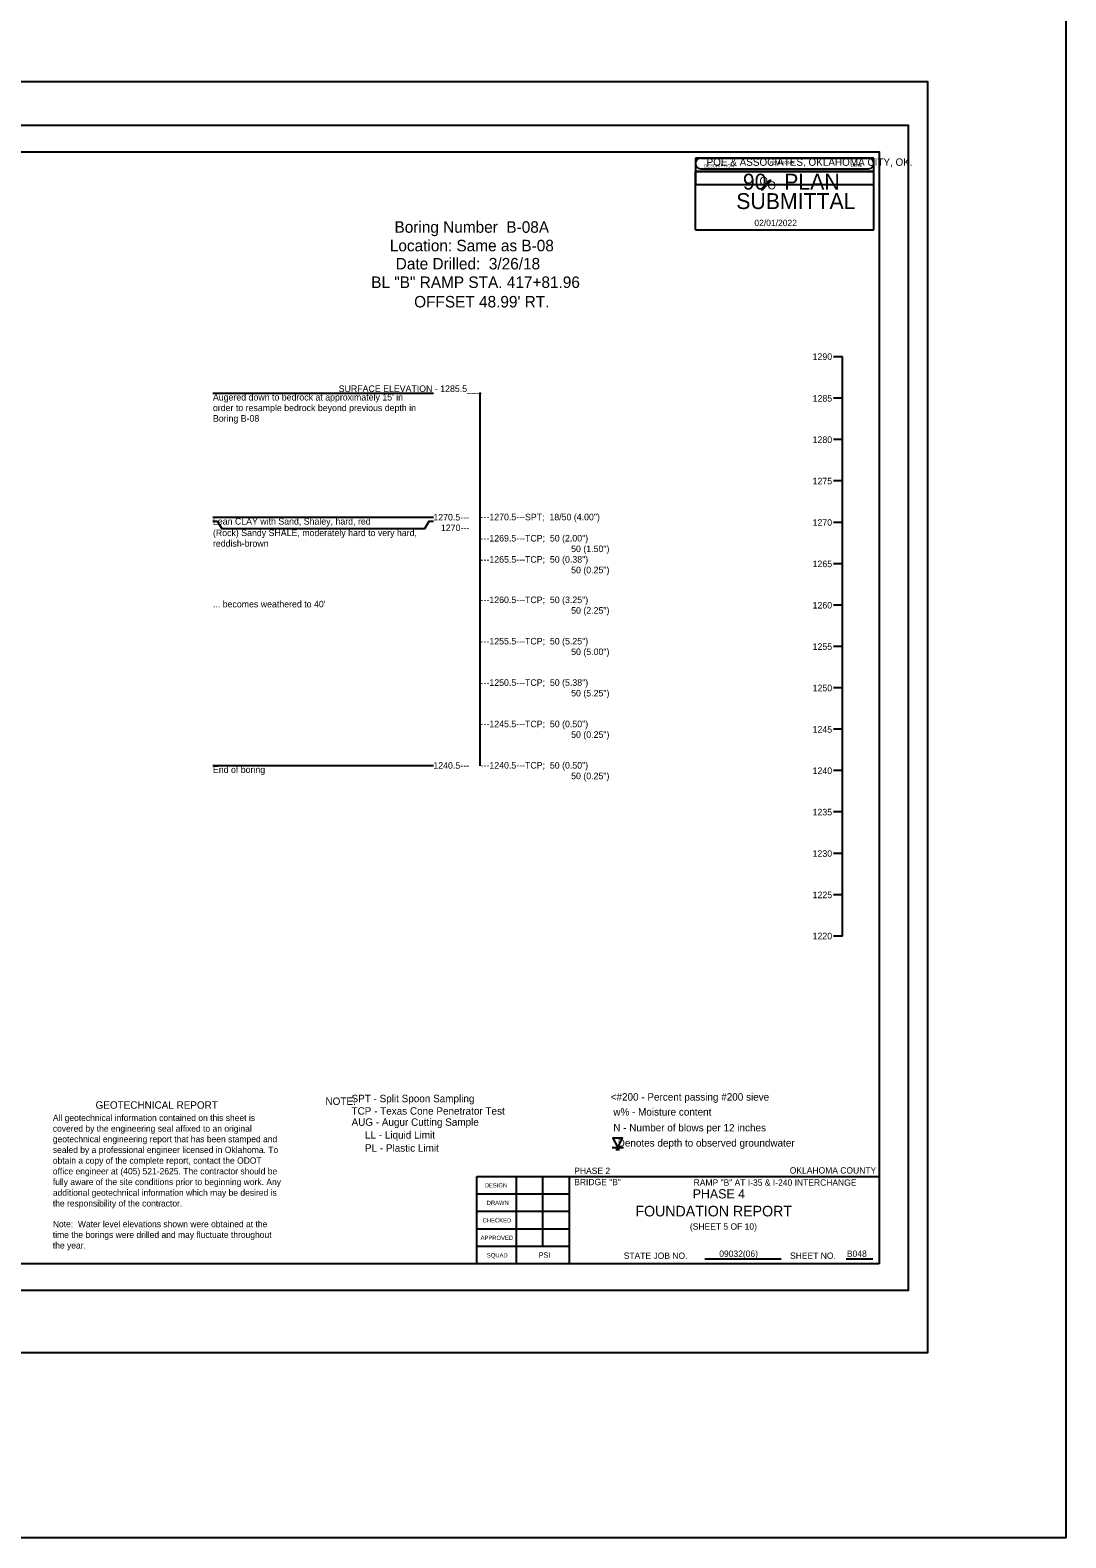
# Model space of a CAD drawing. Extents: x 2150162 to 2150245, y 143729 to 143865.
# Drawn here: x 2150183.85 to 2150203.4, y 143729.32 to 143757.78 of the extents above; entities that cross this region are included whole.
import ezdxf

# ---------------------------------------------------------------- set-up
doc = ezdxf.new("R2010")
doc.units = 0
for name, color, linetype in [('Default', 7, 'Continuous'), ('S', 7, 'Continuous'), ('SHT_Plot_Shape_Full', 7, 'Continuous'), ('SHT_Plot_Shape_Half', 7, 'Continuous'), ('SHT_Sheet_Border', 7, 'Continuous'), ('SHT_Stamp_90_Submit', 7, 'Continuous'), ('SHT_Stamp_Rev_Block', 7, 'Continuous'), ('SHT_Standard_Sheet_Lines', 7, 'Continuous'), ('SHT_Standard_Sheet_Txt', 7, 'Continuous'), ('T', 7, 'Continuous'), ('T-Title', 7, 'Continuous'), ('Text', 7, 'Continuous')]:
    doc.layers.add(name, color=color, linetype=linetype)

# ---------------------------------------------------------------- blocks, each defined once
blk = doc.blocks.new('DGRFC_WTLEV1')
at = {"layer": 'Default'}
for points in [[(-0.0127, 0), (0.0127, 0)], [(0, 0), (0.0106, 0.0212), (-0.0106, 0.0212), (0, 0)], [(-0.0042, -0.0042), (0.0042, -0.0042)]]:
    blk.add_lwpolyline(points, dxfattribs=at)

msp = doc.modelspace()

# ---------------------------------------------------------------- linework, layer by layer
at = {"layer": 'Default'}
msp.add_line((2150199.186, 143740.676), (2150199.186, 143751.613), dxfattribs=at)
for points in [[(2150199.186, 143751.613), (2150199.019, 143751.613)], [(2150187.299, 143750.929), (2150191.466, 143750.929)], [(2150192.338, 143750.937), (2150192.338, 143743.89)], [(2150199.186, 143750.832), (2150199.019, 143750.832)], [(2150199.186, 143750.051), (2150199.019, 143750.051)], [(2150199.186, 143749.27), (2150199.019, 143749.27)], [(2150199.186, 143749.27), (2150199.019, 143749.27)], [(2150187.299, 143748.585), (2150191.466, 143748.585)], [(2150187.299, 143748.507), (2150187.382, 143748.507), (2150187.466, 143748.369), (2150191.299, 143748.369), (2150191.382, 143748.507), (2150191.466, 143748.507)], [(2150199.186, 143748.488), (2150199.019, 143748.488)], [(2150199.186, 143747.707), (2150199.019, 143747.707)], [(2150199.186, 143746.926), (2150199.019, 143746.926)], [(2150199.186, 143746.145), (2150199.019, 143746.145)], [(2150199.186, 143745.363), (2150199.019, 143745.363)], [(2150199.186, 143744.582), (2150199.019, 143744.582)], [(2150187.299, 143743.898), (2150191.466, 143743.898)], [(2150199.186, 143743.801), (2150199.019, 143743.801)], [(2150199.186, 143743.02), (2150199.019, 143743.02)], [(2150199.186, 143742.238), (2150199.019, 143742.238)], [(2150199.186, 143741.457), (2150199.019, 143741.457)], [(2150199.186, 143740.676), (2150199.019, 143740.676)]]:
    msp.add_lwpolyline(points, dxfattribs=at)
at = {"layer": 'S'}
msp.add_lwpolyline([(2150161.568, 143784.341), (2150203.404, 143784.341), (2150203.404, 143729.315), (2150161.568, 143729.315)], close=True, dxfattribs=at)
at = {"layer": 'SHT_Plot_Shape_Full'}
msp.add_lwpolyline([(2150164.792, 143756.811), (2150200.792, 143756.811), (2150200.792, 143732.811), (2150164.792, 143732.811)], close=True, dxfattribs=at)
at = {"layer": 'SHT_Plot_Shape_Half'}
msp.add_lwpolyline([(2150166.429, 143755.986), (2150200.429, 143755.986), (2150200.429, 143733.986), (2150166.429, 143733.986)], close=True, dxfattribs=at)
at = {"layer": 'SHT_Sheet_Border'}
for p, q in [((2150192.279, 143734.486), (2150192.279, 143736.136)), ((2150192.279, 143736.136), (2150199.879, 143736.136)), ((2150194.029, 143734.486), (2150194.029, 143736.136))]:
    msp.add_line(p, q, dxfattribs=at)
msp.add_lwpolyline([(2150199.879, 143734.486), (2150168.379, 143734.486), (2150168.379, 143755.486), (2150199.879, 143755.486)], close=True, dxfattribs=at)
at = {"layer": 'SHT_Stamp_90_Submit'}
for p, q in [((2150196.51, 143755.362), (2150199.676, 143755.362)), ((2150196.41, 143755.112), (2150199.776, 143755.112)), ((2150196.41, 143754.012), (2150196.41, 143755.112)), ((2150196.51, 143755.162), (2150199.676, 143755.162)), ((2150197.653, 143754.773), (2150197.809, 143754.946)), ((2150197.671, 143754.773), (2150197.827, 143754.946)), ((2150197.676, 143754.773), (2150197.832, 143754.946)), ((2150197.684, 143754.773), (2150197.839, 143754.946)), ((2150197.809, 143754.946), (2150197.839, 143754.946)), ((2150199.776, 143754.012), (2150199.776, 143755.112)), ((2150197.653, 143754.773), (2150197.684, 143754.773)), ((2150196.41, 143754.012), (2150199.776, 143754.012))]:
    msp.add_line(p, q, dxfattribs=at)
for centre, start, end in [((2150196.51, 143755.262), 89.9952, 270), ((2150199.676, 143755.262), 270, 90.0048)]:
    msp.add_arc(centre, 0.1, start, end, dxfattribs=at)
at = {"layer": 'SHT_Stamp_Rev_Block'}
for p, q in [((2150196.41, 143755.362), (2150196.41, 143754.862)), ((2150199.776, 143755.362), (2150196.41, 143755.362)), ((2150199.776, 143754.862), (2150199.776, 143755.362)), ((2150199.776, 143755.112), (2150196.41, 143755.112)), ((2150199.776, 143754.862), (2150196.41, 143754.862))]:
    msp.add_line(p, q, dxfattribs=at)
at = {"layer": 'SHT_Standard_Sheet_Lines'}
for p, q in [((2150193.029, 143734.486), (2150193.029, 143736.136)), ((2150193.529, 143734.816), (2150193.529, 143736.136)), ((2150196.59, 143734.582), (2150198.03, 143734.582)), ((2150199.255, 143734.582), (2150199.757, 143734.582))]:
    msp.add_line(p, q, dxfattribs=at)
for points in [[(2150194.029, 143735.806), (2150192.279, 143735.806)], [(2150194.029, 143735.476), (2150192.279, 143735.476)], [(2150194.029, 143735.146), (2150192.279, 143735.146)], [(2150194.029, 143734.816), (2150192.279, 143734.816)]]:
    msp.add_lwpolyline(points, dxfattribs=at)

# ---------------------------------------------------------------- block references
at = {"layer": 'Default', "xscale": 8.503919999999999, "yscale": 8.503919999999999}
msp.add_blockref('DGRFC_WTLEV1', (2150194.943, 143736.684), dxfattribs=at)

# ---------------------------------------------------------------- texts
at = {"layer": 'Default'}
for s, height, p in [('Boring Number  B-08A', 0.217, (2150190.727, 143753.955)), ('Location: Same as B-08', 0.217, (2150190.639, 143753.605)), ('Date Drilled:  3/26/18', 0.217, (2150190.751, 143753.263)), ('BL "B" RAMP STA. 417+81.96', 0.217, (2150190.288, 143752.913)), ("OFFSET 48.99' RT.", 0.217, (2150191.098, 143752.545)), ('1290', 0.124, (2150198.622, 143751.555)), ('SURFACE ELEVATION - 1285.5___', 0.124, (2150189.674, 143750.949)), ("Augered down to bedrock at approximately 15' in", 0.124, (2150187.299, 143750.788)), ('order to resample bedrock beyond previous depth in', 0.124, (2150187.299, 143750.588)), ('1285', 0.124, (2150198.622, 143750.767)), ('Boring B-08', 0.124, (2150187.299, 143750.388)), ('1280', 0.124, (2150198.622, 143749.986)), ('1275', 0.124, (2150198.622, 143749.205)), ('1270.5---', 0.124, (2150191.461, 143748.523)), ('---1270.5---SPT;  18/50 (4.00")', 0.124, (2150192.353, 143748.526)), ('Lean CLAY with Sand, Shaley, hard, red', 0.124, (2150187.299, 143748.445)), ('1270---', 0.124, (2150191.604, 143748.323)), ('1270', 0.124, (2150198.622, 143748.423)), ('(Rock) Sandy SHALE, moderately hard to very hard,', 0.124, (2150187.299, 143748.228)), ('reddish-brown', 0.124, (2150187.299, 143748.028)), ('---1269.5---TCP;  50 (2.00")', 0.124, (2150192.353, 143748.126)), ('---1265.5---TCP;  50 (0.38")', 0.124, (2150192.353, 143747.726)), ('50 (1.50")', 0.124, (2150194.063, 143747.926)), ('50 (0.25")', 0.124, (2150194.063, 143747.526)), ('1265', 0.124, (2150198.622, 143747.642)), ("... becomes weathered to 40'", 0.124, (2150187.299, 143746.882)), ('---1260.5---TCP;  50 (3.25")', 0.124, (2150192.353, 143746.963)), ('1260', 0.124, (2150198.622, 143746.861)), ('50 (2.25")', 0.124, (2150194.063, 143746.763)), ('---1255.5---TCP;  50 (5.25")', 0.124, (2150192.353, 143746.182)), ('50 (5.00")', 0.124, (2150194.063, 143745.982)), ('1255', 0.124, (2150198.622, 143746.08)), ('---1250.5---TCP;  50 (5.38")', 0.124, (2150192.353, 143745.401)), ('50 (5.25")', 0.124, (2150194.063, 143745.201)), ('1250', 0.124, (2150198.622, 143745.298)), ('---1245.5---TCP;  50 (0.50")', 0.124, (2150192.353, 143744.619)), ('50 (0.25")', 0.124, (2150194.063, 143744.419)), ('1245', 0.124, (2150198.622, 143744.517)), ('End of boring', 0.124, (2150187.299, 143743.757)), ('1240.5---', 0.124, (2150191.461, 143743.836)), ('---1240.5---TCP;  50 (0.50")', 0.124, (2150192.353, 143743.838)), ('1240', 0.124, (2150198.622, 143743.736)), ('50 (0.25")', 0.124, (2150194.063, 143743.638)), ('1235', 0.124, (2150198.622, 143742.955)), ('1230', 0.124, (2150198.622, 143742.173)), ('1225', 0.124, (2150198.622, 143741.392)), ('1220', 0.124, (2150198.622, 143740.616))]:
    msp.add_text(s, height=height, dxfattribs=at).set_placement(p)
at = {"layer": 'Defpoints'}
msp.add_text('PHASE 4', height=0.175, dxfattribs=at).set_placement((2150196.358, 143735.723))
at = {"layer": 'SHT_Stamp_90_Submit'}
for s, height, p in [('POE & ASSOCIATES, OKLAHOMA CITY, OK.', 0.14, (2150196.62, 143755.219)), ('90   PLAN', 0.3, (2150197.305, 143754.77)), ('O', 0.153, (2150197.619, 143754.858)), ('O', 0.153, (2150197.771, 143754.774)), ('SUBMITTAL', 0.3, (2150197.181, 143754.403)), ('02/01/2022', 0.12, (2150197.523, 143754.081))]:
    msp.add_text(s, height=height, dxfattribs=at).set_placement(p)
at = {"layer": 'SHT_Stamp_Rev_Block'}
for s, height, p in [('DESCRIPTION', 0.05999, (2150196.57, 143755.19)), ('REVISIONS', 0.06, (2150197.818, 143755.249)), ('DATE', 0.06, (2150199.34, 143755.194))]:
    msp.add_text(s, height=height, dxfattribs=at).set_placement(p)
at = {"layer": 'SHT_Standard_Sheet_Txt'}
for s, height, p in [('DESIGN', 0.08, (2150192.431, 143735.931)), ('DRAWN', 0.08, (2150192.467, 143735.6)), ('CHECKED', 0.08, (2150192.392, 143735.27)), ('APPROVED', 0.08, (2150192.353, 143734.94)), ('STATE JOB NO.', 0.12, (2150195.056, 143734.582)), ('SHEET NO. ', 0.12, (2150198.196, 143734.582)), ('SQUAD', 0.08, (2150192.471, 143734.61))]:
    msp.add_text(s, height=height, dxfattribs=at).set_placement(p)
at = {"layer": 'T'}
for s, height, p in [('PHASE 2', 0.12, (2150194.121, 143736.185)), ('OKLAHOMA COUNTY', 0.12, (2150198.191, 143736.193)), ('BRIDGE "B"', 0.12, (2150194.121, 143735.973)), ('RAMP "B" AT I-35 & I-240 INTERCHANGE', 0.12, (2150196.376, 143735.963)), ('(SHEET 5 OF 10)', 0.12, (2150196.305, 143735.133)), ('PSI', 0.1, (2150193.449, 143734.604)), ('09032(06)', 0.12, (2150196.859, 143734.62)), ('B048', 0.12, (2150199.27, 143734.62))]:
    msp.add_text(s, height=height, dxfattribs=at).set_placement(p)
at = {"layer": 'T-Title'}
msp.add_text('FOUNDATION REPORT', height=0.2, dxfattribs=at).set_placement((2150195.276, 143735.384))
at = {"layer": 'Text'}
for s, height, p in [('GEOTECHNICAL REPORT', 0.14, (2150185.083, 143737.417)), ('NOTE:', 0.14, (2150189.424, 143737.489)), ('    SPT - Split Spoon Sampling', 0.14, (2150189.708, 143737.54)), (' <#200 - Percent passing #200 sieve', 0.14, (2150194.758, 143737.57)), ('All geotechnical information contained on this sheet is ', 0.12, (2150184.276, 143737.185)), ('    TCP - Texas Cone Penetrator Test', 0.14, (2150189.708, 143737.305)), ('w% - Moisture content', 0.14, (2150194.859, 143737.288)), ('covered by the engineering seal affixed to an original ', 0.12, (2150184.276, 143736.983)), ('    AUG - Augur Cutting Sample', 0.14, (2150189.708, 143737.095)), (' LL - Liquid Limit', 0.14, (2150190.118, 143736.853)), ('N - Number of blows per 12 inches', 0.14, (2150194.859, 143736.989)), ('sealed by a professional engineer licensed in Oklahoma. To ', 0.12, (2150184.276, 143736.581)), ('geotechnical engineering report that has been stamped and ', 0.12, (2150184.276, 143736.783)), (' PL - Plastic Limit', 0.14, (2150190.118, 143736.606)), ('    Denotes depth to observed groundwater', 0.14, (2150194.734, 143736.702)), ('obtain a copy of the complete report, contact the ODOT ', 0.12, (2150184.276, 143736.379)), ('office engineer at (405) 521-2625. The contractor should be ', 0.12, (2150184.276, 143736.177)), ('fully aware of the site conditions prior to beginning work. Any ', 0.12, (2150184.276, 143735.975)), ('additional geotechnical information which may be desired is ', 0.12, (2150184.276, 143735.773)), ('the responsibility of the contractor.', 0.12, (2150184.276, 143735.571)), ('Note:  Water level elevations shown were obtained at the ', 0.12, (2150184.276, 143735.18)), ('time the borings were drilled and may fluctuate throughout ', 0.12, (2150184.276, 143734.978)), ('the year.', 0.12, (2150184.276, 143734.778))]:
    msp.add_text(s, height=height, dxfattribs=at).set_placement(p)

doc.saveas('drawing.dxf')
